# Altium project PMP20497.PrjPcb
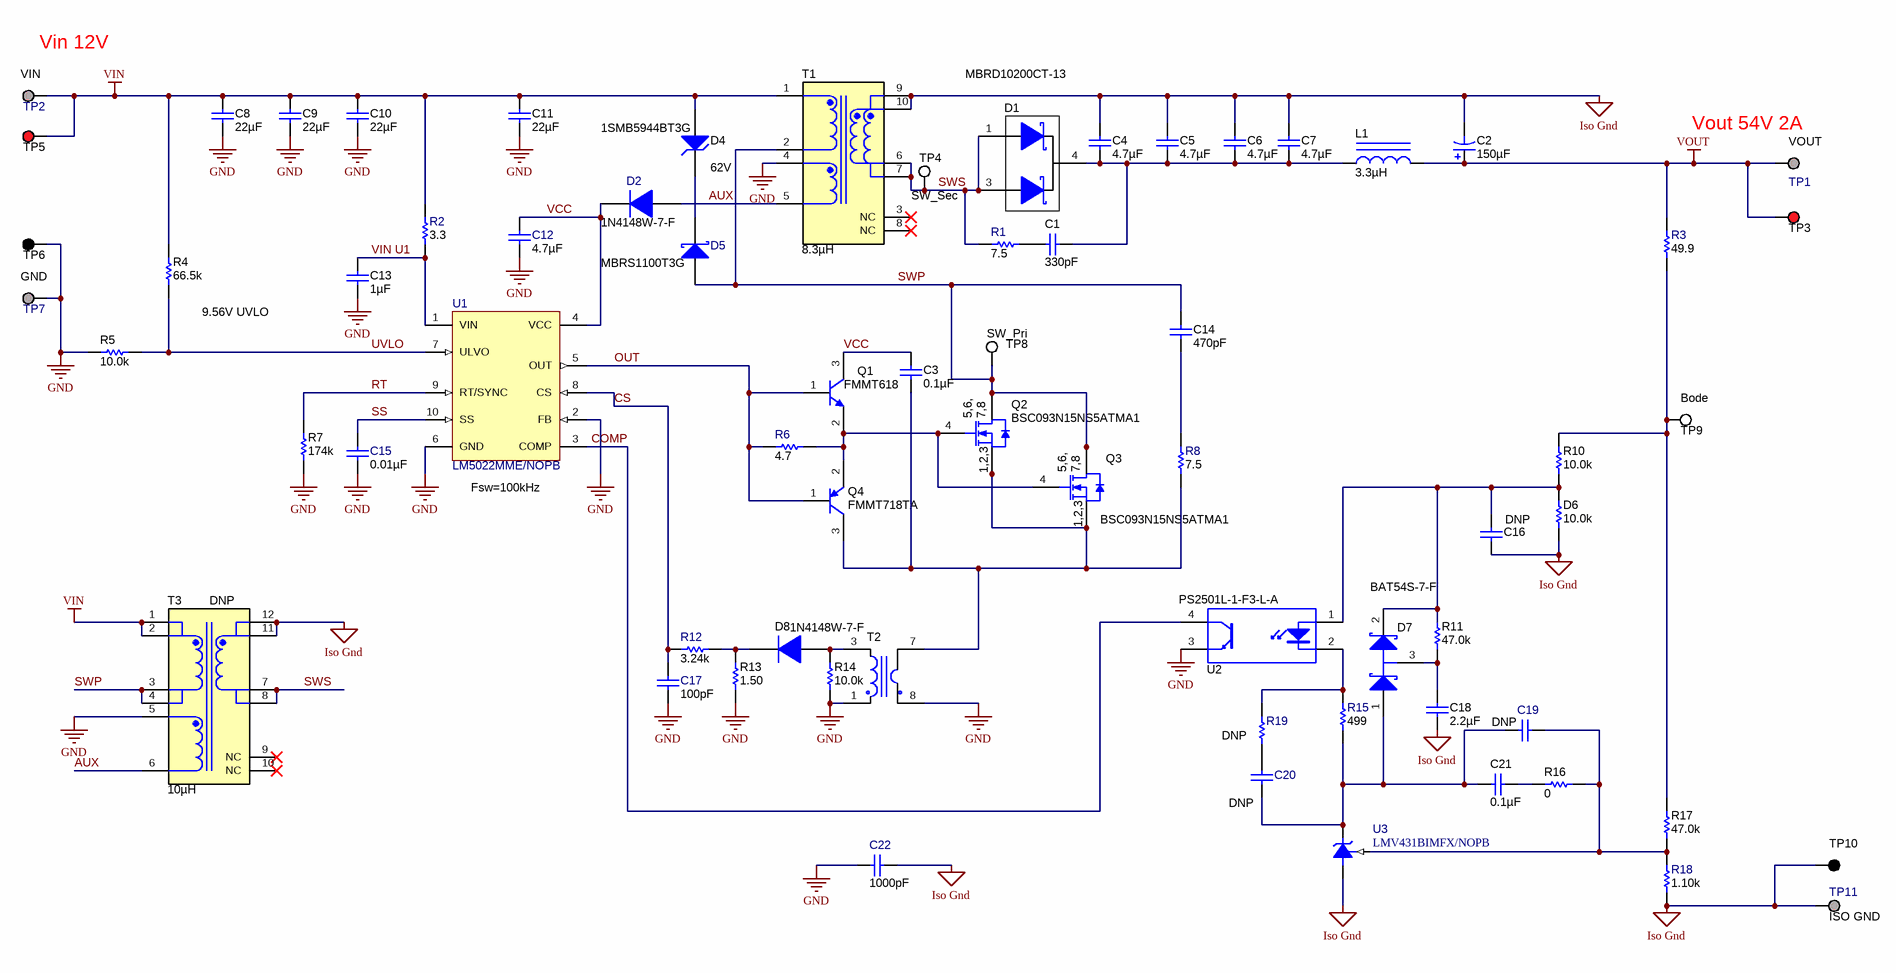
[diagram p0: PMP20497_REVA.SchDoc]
CopyrightYear: 2016; PCB_Layout: Xinyu Dai; PCB_Rev: A; PRJ_Customer: Public Release; PRJ_Engineer: Xinyu Dai; PRJ_Number: PMP20497; PRJ_Title: LM5022 100W Flyback; SCH_Rev: A; TechSupport: http://www.ti.com/support; TID: PMP20497
2 sheets, 82 parts. Net scope: global (net labels, ports and power ports of the same name join across sheets).
Board file: PMP20497_REVA.PcbDoc
Sheets:
  PMP20497_REVA.SchDoc
  PMP20497_REVA_Hardware.SchDoc

## Sheet PMP20497_REVA.SchDoc
size 431 x 279 mm; Date: Not shown in title block; ApprovedBy: Not shown in title block; CheckedBy: Not shown in title block; Author: Not shown in title block; CompanyName: Not shown in title block; Engineer: Not shown in title block; Organization: Not shown in title block; Address1: Not shown in title block; Address2: Not shown in title block; Address3: Not shown in title block; Address4: Not shown in title block; DocumentNumber: 1; Revision: Use project parameter SCH_Rev; SheetNumber: 1; SheetTotal: 2; PageSetup: Record=PageOptions¦CenterHorizontal=True¦CenterVertical=True¦PrintScale=1.00¦XCorrection=1.00¦YCorrection=1.00¦PrintKind=0¦BorderSize=5000000¦LeftOffset=0¦BottomOffset=0¦Orientation=2¦PaperLength=1000¦PaperWidth=1000¦Scale=100¦PaperSource=15¦PrintQuality=600¦MediaType=1¦DitherType=10¦PaperKind=Letter¦PrintScaleMode=1

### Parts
C1  ValueDisplayed: 330pF  [0805L]  (hidden comment: GRM2165C2A331JA01D)
C2  ValueDisplayed: 150µF  [SM_RADIAL_H13]  (hidden comment: EEV-FK1J151Q)
C3  ValueDisplayed: 0.1µF  [0603L]  (hidden comment: GRM188R71C104KA01D)
C4  ValueDisplayed: 4.7µF  [1210_270L]  (hidden comment: GRM32ER71K475KE14L)
C5  ValueDisplayed: 4.7µF  [1210_270L]  (hidden comment: GRM32ER71K475KE14L)
C6  ValueDisplayed: 4.7µF  [1210_270L]  (hidden comment: GRM32ER71K475KE14L)
C7  ValueDisplayed: 4.7µF  [1210_270L]  (hidden comment: GRM32ER71K475KE14L)
C8  ValueDisplayed: 22µF  [1210_270L]  (hidden comment: GRM32ER71E226KE15L)
C9  ValueDisplayed: 22µF  [1210_270L]  (hidden comment: GRM32ER71E226KE15L)
C10  ValueDisplayed: 22µF  [1210_270L]  (hidden comment: GRM32ER71E226KE15L)
C11  ValueDisplayed: 22µF  [1210_270L]  (hidden comment: GRM32ER71E226KE15L)
C12  ValueDisplayed: 4.7µF  [0805L]  (hidden comment: GRM21BR71C475KA73L)
C13  ValueDisplayed: 1µF  [0603L]  (hidden comment: GRM188R71E105KA12D)
C14  ValueDisplayed: 470pF  [0805_HV]  (hidden comment: GRM2165C2A471JA01D)
C15  ValueDisplayed: 0.01µF  [0603L]  (hidden comment: GRM188R71C103KA01D)
C16  DNP  [0603L]
C17  ValueDisplayed: 100pF  [0603L]  (hidden comment: GRM1885C1H101JA01D)
C18  ValueDisplayed: 2.2µF  [0805L]  (hidden comment: UMK212BB7225KG-T)
C19  DNP  [0603L]
C20  DNP  [0603L]
C21  ValueDisplayed: 0.1µF  [0603L]  (hidden comment: GRM188R71E104KA01D)
C22  ValueDisplayed: 1000pF  [1206L]  (hidden comment: GRM31BR73A102KW01L)
D1  MBRD10200CT-13  [DPAK]
D2  (no value)  [SOD-123]
D4  1SMB5944BT3G  value 62V  [SMB]
D5  MBRS1100T3G  [SMB]
D6  ValueDisplayed: 10.0k  [0805L]  (hidden comment: CRCW080510K0FKEA)
D7  BAT54S-7-F  [SOT-23L]
D8  1N4148W-7-F  [SOD-123]
L1  ValueDisplayed: 3.3µH  [SRR6028]  (hidden comment: SRR6028-3R3Y)
Q1  FMMT618  [SOT-23L]
Q2  BSC093N15NS5ATMA1  [PG-TDSON-8]
Q3  BSC093N15NS5ATMA1  [PG-TDSON-8]
Q4  FMMT718TA  [SOT-23L]
R1  ValueDisplayed: 7.5  [2010L]  (hidden comment: CRCW20107R50JNEF)
R2  ValueDisplayed: 3.3  [0805L]  (hidden comment: CRCW08053R30JNEA)
R3  ValueDisplayed: 49.9  [0603L]  (hidden comment: CRCW060349R9FKEA)
R4  ValueDisplayed: 66.5k  [0603L]  (hidden comment: CRCW060366K5FKEA)
R5  value 10.0k  [0603L]  (hidden comment: CRCW060310K0FKEA)
R6  ValueDisplayed: 4.7  [0603L]  (hidden comment: CRCW06034R70JNEA)
R7  ValueDisplayed: 174k  [0603L]  (hidden comment: CRCW0603174KFKEA)
R8  ValueDisplayed: 7.5  [2010L]  (hidden comment: CRCW20107R50JNEF)
R10  ValueDisplayed: 10.0k  [0805L]  (hidden comment: CRCW080510K0FKEA)
R11  ValueDisplayed: 47.0k  [0603L]  (hidden comment: CRCW060347K0FKEA)
R12  ValueDisplayed: 3.24k  [0603L]  (hidden comment: CRCW06033K24FKEA)
R13  ValueDisplayed: 1.50  [0603L]  (hidden comment: CRCW06031R50FKEA)
R14  value 10.0k  [0603L]  (hidden comment: CRCW060310K0FKEA)
R15  ValueDisplayed: 499  [0603L]  (hidden comment: CRCW0603499RFKEA)
R16  ValueDisplayed: 0  [0603]  (hidden comment: CRCW06030000Z0EA)
R17  ValueDisplayed: 47.0k  [0603L]  (hidden comment: CRCW060347K0FKEA)
R18  ValueDisplayed: 1.10k  [0603L]  (hidden comment: CRCW06031K10FKEA)
R19  DNP  [0603L]
T1  ValueDisplayed: 8.3µH  [Pulse_PA4826NL]  (hidden comment: PA4826NL)
T2  PA1005.100NL  [P82xx]  (value not drawn)
T3  DNP  ValueDisplayed: 10µH  [Pulse_PA4621NL]
TP1  VOUT  [Keystone1502-2]
TP2  VIN  [Keystone1502-2]
TP3  5000  [Keystone5000]  (value not drawn)
TP4  SW_Sec  [Keystone5002]
TP5  5000  [Keystone5000]  (value not drawn)
TP6  5001  [Keystone5001]  (value not drawn)
TP7  GND  [Keystone1502-2]
TP8  SW_Pri  [Keystone5002]
TP9  Bode  [Keystone5002]
TP10  5001  [Keystone5001]  (value not drawn)
TP11  ISO GND  [Keystone1502-2]
U1  LM5022MME/NOPB  [MUB10A_N]
U2  PS2501L-1-F3-L-A  [PS2501L]
U3  LMV431BIMFX/NOPB  [MF03A_N]

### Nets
GND: C8.2 C9.2 C10.2 C11.2 C12.2 C13.2 C15.2 C17.2 C22.2 R5.1 R7.1 R13.1 R14.1 T1.4 T2.1 T2.8 T3.5 TP6.1 TP7.1 U1.2(FB) U1.6(GND) U2.3(E)
Iso Gnd: C2.2(-) C4.1 C5.1 C6.1 C7.1 C16.2 C18.2 C22.1 D6.1 R18.2 T1.9 T1.10 T3.11 T3.12 TP10.1 TP11.1 U3.3(A)
VIN: C8.1 C9.1 C10.1 C11.1 D4.2(A) R2.2 R4.2 T1.1 T3.1 T3.2 TP2.1 TP5.1
VOUT: C2.1(+) L1.2 R3.2 TP1.1 TP3.1
AUX: D2.2(A) T1.5 T3.6
COMP: U1.3(COMP) U2.4(C)
CS: C17.1 R12.1 U1.8(CS)
OUT: Q1.1(B) Q4.1(B) R6.1 U1.5(OUT)
RT: R7.2 U1.9(RT/SYNC)
SS: C15.1 U1.10(SS)
SWP: C14.1 D5.2(A) Q2.5(D) Q2.6(D) Q2.7(D) Q2.8(D) Q2.9(D) Q3.5(D) Q3.6(D) Q3.7(D) Q3.8(D) Q3.9(D) T1.2 T3.3 T3.4 TP8.1
SWS: D1.1(A) D1.3(A) R1.2 T1.6 T1.7 T3.7 T3.8 TP4.1
UVLO: R4.1 R5.2 U1.7(ULVO)
VCC: C3.1 C12.1 D2.1(K) Q1.3(C) U1.4(VCC)
VIN U1: C13.1 R2.1 U1.1(VIN)
NetC1_1: C1.1 C4.2 C5.2 C6.2 C7.2 D1.4(K) L1.1
NetC1_2: C1.2 R1.1
NetC3_2: C3.2 Q2.1(S) Q2.2(S) Q2.3(S) Q3.1(S) Q3.2(S) Q3.3(S) Q4.3(C) R8.2 T2.7
NetC14_2: C14.2 R8.1
NetC16_1: C16.1 D6.2 D7.2(K) R10.1 R11.2 U2.1(A)
NetC18_1: C18.1 D7.3(C) R11.1
NetC19_1: C19.1 C20.1 C21.2 D7.1(A) R15.2 U3.2(K)
NetC19_2: C19.2 R16.1 R17.1 R18.1 U3.1(REF)
NetC20_2: C20.2 R19.2
NetC21_1: C21.1 R16.2
NetD4_1: D4.1(K) D5.1(K)
NetD8_1: D8.1(K) R12.2 R13.2
NetD8_2: D8.2(A) R14.2 T2.3
NetQ1_2: Q1.2(E) Q2.4(G) Q3.4(G) Q4.2(E) R6.2
NetR3_1: R3.1 R10.2 R17.2 TP9.1
NetR15_1: R15.1 R19.1 U2.2(K)

Not connected (* = marked no-connect by the designer): T1 3(NC)* 8(NC)*; T3 9(NC)* 10(NC)*

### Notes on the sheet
- (near TP2) Vin 12V
- (near TP1) Vout 54V 2A
- (near R4) 9.56V UVLO
- (near U1) Fsw=100kHz

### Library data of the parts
C1 = GRM2165C2A331JA01D: CAP, CERM, 330 pF, 100 V, +/- 5%, C0G/NP0, 0805; Manufacturer: MuRata; Polarized: N; CompType: Capacitor; Value: 330pF; U/M: EA; Cap_F: 0.00000000033; Tolerance_%: 5; Value1: Unknown; VDC_V: 100; Value2: 100V; TaMin_C: -55; TaMax_C: 125; Cap_Case: 0805; AEC Category: Q200; SizeArea_mm2: 2.5; SizeAreaWB_mm2: 6.75; SizeX_mm: 2; SizeY_mm: 1.25; SizeZ_mm: 1.45
C2 = EEV-FK1J151Q: CAP, AL, 150uF, 63V, +/-20%, 0.16 ohm, SMD; Manufacturer: Panasonic; Polarized: Y; CompType: Capacitor; U/M: EA; Cap_F: 0.00015; Tolerance_%: 20; VDC_V: 63; ESR_Ohm: 0.16; IRMS_A: 0.8; TaMin_C: -55; TaMax_C: 105; Cap_Case: H13
C3 = GRM188R71C104KA01D: CAP, CERM, 0.1 µF, 16 V, +/- 10%, X7R, 0603; Manufacturer: MuRata; Polarized: N; CompType: Capacitor; Value: 0.1uF; U/M: EA; Cap_F: 0.0000001; Tolerance_%: 10; Value1: Unknown; VDC_V: 16; Value2: 16V; TaMin_C: -55; TaMax_C: 125; Cap_Case: 0603; SizeArea_mm2: 1.28; SizeAreaWB_mm2: 4.68; SizeX_mm: 1.6; SizeY_mm: 0.8; SizeZ_mm: 1; AEC Category: Q200
C4-C7 = GRM32ER71K475KE14L: CAP, CERM, 4.7 µF, 80 V, +/- 10%, X7R, 1210; Manufacturer: MuRata; Polarized: N; CompType: Capacitor; Value: 4.7uF; U/M: EA; Cap_F: 0.0000047; Tolerance_%: 10; Value1: Unknown; VDC_V: 80; Value2: 80V; TaMin_C: -55; TaMax_C: 125; Cap_Case: 1210; SizeArea_mm2: 8; SizeAreaWB_mm2: 14.7; SizeX_mm: 3.2; SizeY_mm: 2.5; SizeZ_mm: 2.7; AEC Category: Q200
C8-C11 = GRM32ER71E226KE15L: CAP, CERM, 22 µF, 25 V, +/- 10%, X7R, 1210; Manufacturer: MuRata; Polarized: N; CompType: Capacitor; Value: 22uF; U/M: EA; Cap_F: 0.000022; Tolerance_%: 10; Value1: Unknown; VDC_V: 25; Value2: 25V; TaMin_C: -55; TaMax_C: 125; Cap_Case: 1210; SizeArea_mm2: 8; SizeAreaWB_mm2: 14.7; SizeX_mm: 3.2; SizeY_mm: 2.5; SizeZ_mm: 2.7; AEC Category: Q200
C12 = GRM21BR71C475KA73L: CAP, CERM, 4.7 µF, 16 V, +/- 10%, X7R, 0805; Manufacturer: MuRata; Cap_Case: 0805; ESR_ohm: 0.006; Polarized: N; TaMax_C: 125; TaMin_C: -55; Tolerance_%: 10; VDC_V: 16; Cap_F: 0.0000047; CompType: Capacitor; Value: 4.7uF; U/M: EA; Value1: 0.006 ohm; Value2: 16V; SizeArea_mm2: 2.5; SizeAreaWB_mm2: 6.75; SizeX_mm: 2; SizeY_mm: 1.25; SizeZ_mm: 1.45; AEC Category: Q200
C13 = GRM188R71E105KA12D: CAP, CERM, 1 µF, 25 V, +/- 10%, X7R, 0603; Manufacturer: MuRata; Polarized: N; CompType: Capacitor; Value: 1uF; U/M: EA; Cap_F: 0.000001; Tolerance_%: 10; Value1: Unknown; VDC_V: 25; Value2: 25V; TaMin_C: -55; TaMax_C: 125; Cap_Case: 0603; SizeArea_mm2: 1.28; SizeAreaWB_mm2: 4.68; SizeX_mm: 1.6; SizeY_mm: 0.8; SizeZ_mm: 1; AEC Category: Q200
C14 = GRM2165C2A471JA01D: CAP, CERM, 470 pF, 100 V, +/- 5%, C0G/NP0, 0805; Manufacturer: MuRata; Polarized: N; CompType: Capacitor; Value: 470pF; U/M: EA; Cap_F: 0.00000000047; Tolerance_%: 5; Value1: Unknown; VDC_V: 100; Value2: 100V; TaMin_C: -55; TaMax_C: 125; Cap_Case: 0805; SizeArea_mm2: 2.5; SizeAreaWB_mm2: 6.75; SizeX_mm: 2; SizeY_mm: 1.25; SizeZ_mm: 1.45; AEC Category: Q200
C15 = GRM188R71C103KA01D: CAP, CERM, 0.01 µF, 16 V, +/- 10%, X7R, 0603; Manufacturer: MuRata; Cap_Case: 0603; Polarized: N; TaMax_C: 125; TaMin_C: -55; Tolerance_%: 10; VDC_V: 16; Cap_F: 0.00000001; CompType: Capacitor; Value: 0.01uF; Value1: Unknown; Value2: 16V; U/M: EA; SizeArea_mm2: 1.28; SizeAreaWB_mm2: 4.68; SizeX_mm: 1.6; SizeY_mm: 0.8; SizeZ_mm: 1; AEC Category: Q200
C16 = GRM188R61C105KA93D: CAP, CERM, 1uF, 16V, +/-10%, X5R, 0603; Manufacturer: MuRata; Polarized: N; CompType: Capacitor; ValueDisplayed: 1µF; U/M: EA; Cap_F: 0.000001; Tolerance_%: 10; VDC_V: 16; TaMin_C: -55; TaMax_C: 85; Cap_Case: 0603
C17 = GRM1885C1H101JA01D: CAP, CERM, 100 pF, 50 V, +/- 5%, C0G/NP0, 0603; Manufacturer: MuRata; Cap_Case: 0603; Polarized: N; TaMax_C: 125; TaMin_C: -55; Tolerance_%: 5; VDC_V: 50; Cap_F: 0.0000000001; CompType: Capacitor; Value: 100pF; Value1: Unknown; Value2: 50V; U/M: EA; SizeArea_mm2: 1.28; SizeAreaWB_mm2: 4.68; SizeX_mm: 1.6; SizeY_mm: 0.8; SizeZ_mm: 1; AEC Category: Q200
C18 = UMK212BB7225KG-T: CAP, CERM, 2.2 µF, 50 V, +/- 10%, X7R, 0805; Manufacturer: Taiyo Yuden; Polarized: N; CompType: Capacitor; Value: 2.2uF; U/M: EA; Cap_F: 0.0000022; Tolerance_%: 10; Value1: Unknown; VDC_V: 50; Value2: 50V; TaMin_C: -55; TaMax_C: 125; Cap_Case: 0805; AEC Category: Q200; SizeArea_mm2: 2.5; SizeAreaWB_mm2: 6.75; SizeX_mm: 2; SizeY_mm: 1.25; SizeZ_mm: 1.45
C19 = GRM188R71H332KA01D: CAP, CERM, 3300 pF, 50 V, +/- 10%, X7R, 0603; Manufacturer: MuRata; Cap_Case: 0603; Polarized: N; TaMax_C: 125; TaMin_C: -55; Tolerance_%: 10; VDC_V: 50; Cap_F: 0.0000000033; CompType: Capacitor; Value: 3300pF; Value1: Unknown; Value2: 50V; U/M: EA; AEC Category: Q200; SizeArea_mm2: 1.28; SizeAreaWB_mm2: 4.68; SizeX_mm: 1.6; SizeY_mm: 0.8; SizeZ_mm: 1
C20 = GRM188R71E473KA01D: CAP, CERM, 0.047 µF, 25 V, +/- 10%, X7R, 0603; Manufacturer: MuRata; Cap_Case: 0603; Polarized: N; TaMax_C: 125; TaMin_C: -55; Tolerance_%: 10; VDC_V: 25; Cap_F: 0.000000047; CompType: Capacitor; Value: 0.047uF; Value1: Unknown; Value2: 25V; U/M: EA; AEC Category: Q200
C21 = GRM188R71E104KA01D: CAP, CERM, 0.1 µF, 25 V, +/- 10%, X7R, 0603; Manufacturer: MuRata; Polarized: N; CompType: Capacitor; Value: 0.1uF; U/M: EA; Cap_F: 0.0000001; Tolerance_%: 10; Value1: Unknown; VDC_V: 25; Value2: 25V; TaMin_C: -55; TaMax_C: 125; Cap_Case: 0603; AEC Category: Q200
C22 = GRM31BR73A102KW01L: CAP, CERM, 1000 pF, 1000 V, +/- 10%, X7R, 1206; Manufacturer: MuRata; Cap_Case: 1206; Polarized: N; TaMax_C: 125; TaMin_C: -55; Tolerance_%: 10; VDC_V: 1000; Cap_F: 0.000000001; CompType: Capacitor; Value: 1000pF; Value1: Unknown; Value2: 1000V; U/M: EA; SizeArea_mm2: 5.12; SizeAreaWB_mm2: 10.92; SizeX_mm: 3.2; SizeY_mm: 1.6; SizeZ_mm: 1.35; AEC Category: Q200
D1 = MBRD10200CT-13: Diode, Schottky, 200 V, 5 A, DPAK; Manufacturer: Diodes Inc.; U/M: EA; Value1: 5A; Value: 200V; Vf_V: 0.91; Value2: 0.91V; Io_A: 5; Vr_V: 200; TJmax_C: 175; RJC_CperW: 6; AEC Category: Q101
D2 = 1N4148W-7-F: Diode, Ultrafast, 100V, 0.15A, SOD-123; Manufacturer: Diodes Inc.; U/M: EA; Vf_V: 1.25; Io_A: 0.15; Vr_V: 100; TJmax_C: 150; Value: 1.25V
D4 = 1SMB5944BT3G: Diode, Zener, 62 V, 550 mW, SMB; Manufacturer: ON Semiconductor; U/M: EA; Power_W: 0.55; Value1: 0.55W; RJA_CperW: 226; SymbolCreator: a0412235; Vz_V: 62; AEC Category: Q101
D5 = MBRS1100T3G: Diode, Schottky, 100 V, 1 A, SMB; Manufacturer: ON Semiconductor; RJC_CperW: 22; Vf_V: 0.75; Io_A: 1; Vr_V: 100; TJmax_C: 150; Value: 100V; U/M: EA; Value1: 1A; Value2: 0.75V
D6 R10 = CRCW080510K0FKEA: RES, 10.0 k, 1%, 0.125 W, 0805; Manufacturer: Vishay-Dale; CompType: Resistor; Value: 10.0k; Res_ohm: 10000; Value_Code: 10k0; Tolerance_%: 1; Power_W: 0.125; Value2: 0.125W; VDC_V: 150; TempCo: 100 ppm/C; EIA_Code: E96; U/M: EA; SizeArea_mm2: 2.5; SizeX_mm: 2; SizeY_mm: 1.25; SizeZ_mm: 1.45; AEC Category: Q200
D7 = BAT54S-7-F: Diode, Schottky, 30 V, 0.2 A, SOT-23; Manufacturer: Diodes Inc.; U/M: EA; Vf_V: 0.65; Value: 30V; Value1: 0.2A; Value2: 0.65V; Io_A: 0.2; Vr_V: 30; TJmax_C: 125; SizeAreaWB_mm2: 14; SizeArea_mm2: 7.5; SizeX_mm: 2.5; SizeY_mm: 3; SizeZ_mm: 1.1; AEC Category: Q101
D8 = 1N4148W-7-F: Diode, Ultrafast, 100 V, 0.15 A, SOD-123; Manufacturer: Diodes Inc.; Value: 100V; U/M: EA; Vf_V: 1.25; Io_A: 0.15; Value1: 0.15A; Vr_V: 100; Value2: 1.25V; TJmax_C: 150; AEC Category: Q101
L1 = SRR6028-3R3Y: Inductor, Drum Core, Ferrite, 3.3 µH, 2.5 A, 0.028 ohm, SMD; Manufacturer: Bourns; Value: 3.3uH; Ind_H: 3.3E-6; Imax_A: 2.5; Irms: 2.5A @ 30C rise; Isat: 2.6A @ 35% inductance drop; DCR_ohm: 0.028; Value2: 2.5A; SizeAreaWB_mm2: 77.44; SizeArea_mm2: 46.24; SizeX_mm: 6.8; SizeZ_mm: 2.8; AEC Category: Q200
Q1 = FMMT618: Transistor, NPN, 20V, 1.5A, SOT-23; Manufacturer: Diodes Inc.; CompType: BJT; PNP: 1; NPN: 0; Vceo_V: 20; Vcesat1_V: 0.25; Value: 0.22V; IcRated_A: 0.2; HfeMax: 400; Vce Saturation (Max) @ Ib, Ic: 220mV @ 50mA, 1.5A; Current - Collector Cutoff (Max): 100nA; DC Current Gain (hFE) (Min) @ Ic, Vce: 300 @ 100mA, 2V; Power - Max: 625mW; Frequency - Transition: 180MHz
Q2 Q3 = BSC093N15NS5ATMA1: MOSFET, N-CH, 150 V, 87 A, PG-TDSON-8; Manufacturer: Infineon Technologies; Alternate Manufacturer: None; Value: 150V; U/M: EA; ChType: N; VdsMax_V: 150; Value1: ? ohm; Value2: 33 nC; QgTyp_nC: 33; Vgs_V: 20; IdsMax_A: 87; AEC Category: Q101; SizeAreaWB_mm2: 55.131; SizeArea_mm2: 29.351; SizeX_mm: 5.99; SizeY_mm: 4.9; SizeZ_mm: 1.12
Q4 = FMMT718TA, Diodes Inc.: Transistor, PNP, 20 V, 1.5 A, SOT-23; CompType: BJT; PNP: 1; NPN: 0; Vceo_V: 20; Value: 20 V; IcRated_A: 1.5; Value1: 1.5 A; HfeMax: 6; TaMin_C: -55; TaMax_C: 150; U/M: EA; AEC Category: Q101
R1 R8 = CRCW20107R50JNEF: RES, 7.5, 5%, 0.75 W, AEC-Q200 Grade 0, 2010; Manufacturer: Vishay-Dale; CompType: Resistor; Tolerance_%: 5; VDC_V: 400; Power_W: 0.75; Value: 7.5; Value_Code: 7R50; Value2: 0.75W; TempCo: 200 ppm/C; EIA_Code: E24; U/M: EA; AEC Category: Q200; AEC Qualified: Y; AEC Grade: 0; SizeArea_mm2: 12.5; SizeY_mm: 2.5; SizeZ_mm: 1.66
R2 = CRCW08053R30JNEA: RES, 3.3, 5%, 0.125 W, 0805; Manufacturer: Vishay-Dale; CompType: Resistor; Tolerance_%: 5; VDC_V: 150; Power_W: 0.125; Value: 3.3; Value_Code: 3R30; Value2: 0.125W; EIA_Code: E24; U/M: EA; TempCo: 200 ppm/C; SizeArea_mm2: 2.5; SizeX_mm: 2; SizeY_mm: 1.25; SizeZ_mm: 1.45; AEC Category: Q200
R3 = CRCW060349R9FKEA: RES, 49.9, 1%, 0.1 W, 0603; Manufacturer: Vishay-Dale; CompType: Resistor; Tolerance_%: 1; VDC_V: 75; Power_W: 0.1; Value: 49.9; Value_Code: 49R9; Value2: 0.1W; EIA_Code: E96; U/M: EA; TempCo: 100 ppm/C; SizeArea_mm2: 1.28; SizeX_mm: 1.6; SizeY_mm: 0.8; AEC Category: Q200
R4 = CRCW060366K5FKEA: RES, 66.5 k, 1%, 0.1 W, 0603; Manufacturer: Vishay-Dale; CompType: Resistor; Value: 66.5k; Res_ohm: 66500; Value_Code: 66k5; Tolerance_%: 1; Power_W: 0.1; Value2: 0.1W; VDC_V: 75; TempCo: 100 ppm/C; EIA_Code: E96; U/M: EA; SizeArea_mm2: 1.28; SizeX_mm: 1.6; SizeY_mm: 0.8; AEC Category: Q200
R5 R14 = CRCW060310K0FKEA: RES, 10.0k ohm, 1%, 0.1W, 0603; Manufacturer: Vishay-Dale; CompType: Resistor; Res_ohm: 10000; Value_Code: 10k0; Tolerance_%: 1; Power_W: 0.1; VDC_V: 75; TempCo: 100 ppm/C; EIA_Code: E96; U/M: EA
R6 = CRCW06034R70JNEA: RES, 4.7, 5%, 0.1 W, 0603; Manufacturer: Vishay-Dale; CompType: Resistor; Tolerance_%: 5; VDC_V: 75; Power_W: 0.1; Value: 4.7; Value_Code: 4R70; Value2: 0.1W; TempCo: 200 ppm/C; EIA_Code: E24; U/M: EA; AEC Category: Q200; SizeArea_mm2: 1.28; SizeX_mm: 1.6; SizeY_mm: 0.8; SizeZ_mm: 1
R7 = CRCW0603174KFKEA: RES, 174 k, 1%, 0.1 W, 0603; Manufacturer: Vishay-Dale; CompType: Resistor; Value: 174k; Res_ohm: 174000; Tolerance_%: 1; Power_W: 0.1; Value2: 0.1W; VDC_V: 75; TempCo: 100 ppm/C; EIA_Code: E96; U/M: EA; AEC Category: Q200
R11 = CRCW060347K0FKEA: RES, 47.0 k, 1%, 0.1 W, AEC-Q200 Grade 0, 0603; Manufacturer: Vishay-Dale; CompType: Resistor; Value: 47.0k; Res_ohm: 47000; Value_Code: 47k0; Tolerance_%: 1; Power_W: 0.1; Value2: 0.1W; VDC_V: 75; TempCo: 100 ppm/C; U/M: EA; SizeArea_mm2: 1.28; SizeX_mm: 1.6; SizeY_mm: 0.8; AEC Category: Q200; AEC Qualified: Y; AEC Grade: 0
R12 = CRCW06033K24FKEA: RES, 3.24 k, 1%, 0.1 W, 0603; Manufacturer: Vishay-Dale; CompType: Resistor; Tolerance_%: 1; VDC_V: 75; Power_W: 0.1; Res_ohm: 3240; Value: 3.24k; Value_Code: 3k24; Value2: 0.1W; TempCo: 100 ppm/C; EIA_Code: E96; U/M: EA; AEC Category: Q200; SizeArea_mm2: 1.28; SizeX_mm: 1.6; SizeY_mm: 0.8
R13 = CRCW06031R50FKEA: RES, 1.50, 1%, 0.1 W, 0603; Manufacturer: Vishay-Dale; CompType: Resistor; Value: 1.50; Res_ohm: 1.5; Value_Code: 1R50; Tolerance_%: 1; Power_W: 0.1; Value2: 0.1W; VDC_V: 75; TempCo: 100 ppm/C; EIA_Code: E96; U/M: EA; AEC Category: Q200; SizeArea_mm2: 1.28; SizeX_mm: 1.6; SizeY_mm: 0.8
R15 = CRCW0603499RFKEA: RES, 499, 1%, 0.1 W, 0603; Manufacturer: Vishay-Dale; CompType: Resistor; Tolerance_%: 1; VDC_V: 75; Power_W: 0.1; Value: 499; Value_Code: 499R; Value2: 0.1W; TempCo: 100 ppm/C; EIA_Code: E96; U/M: EA; SizeArea_mm2: 1.28; SizeX_mm: 1.6; SizeY_mm: 0.8; AEC Category: Q200
R16 = CRCW06030000Z0EA: RES, 0, 5%, 0.1 W, 0603; Manufacturer: Vishay-Dale; CompType: Resistor; Value: 0; Value_Code: 0000; Tolerance_%: 5; Power_W: 0.1; Value2: 0.1W; VDC_V: 75; TempCo: 200 ppm/C; EIA_Code: E24; U/M: EA; AEC Category: Q200; SizeArea_mm2: 1.28; SizeX_mm: 1.6; SizeY_mm: 0.8; SizeZ_mm: 1
R17 = CRCW060347K0FKEA: RES, 47.0 k, 1%, 0.1 W, AEC-Q200 Grade 0, 0603; Manufacturer: Vishay-Dale; CompType: Resistor; Value: 47.0k; Res_ohm: 47000; Value_Code: 47k0; Tolerance_%: 1; Power_W: 0.1; Value2: 0.1W; VDC_V: 75; TempCo: 100 ppm/C; U/M: EA; AEC Category: Q200; AEC Qualified: Y; AEC Grade: 0; SizeArea_mm2: 1.28; SizeX_mm: 1.6; SizeY_mm: 0.8
R18 R19 = CRCW06031K10FKEA: RES, 1.10 k, 1%, 0.1 W, 0603; Manufacturer: Vishay-Dale; CompType: Resistor; Tolerance_%: 1; VDC_V: 75; Power_W: 0.1; Res_ohm: 1100; Value: 1.10k; Value_Code: 1k10; Value2: 0.1W; TempCo: 100 ppm/C; EIA_Code: E96; U/M: EA; AEC Category: Q200; SizeArea_mm2: 1.28; SizeX_mm: 1.6; SizeY_mm: 0.8
T1 = PA4826NL: Transformer, 8.3 uH, TH; Manufacturer: Pulse Engineering; SymbolCreator: Altium; Value: 8.3uH; Lp: 8.3; DCR_ohm: 0.0035; LeakageL: 0.15; Ns1toNp: 1.25; Ns2toNp: 0.25; Rs1: 0.04; Rs2: 0.0525; SizeAreaWB_mm2: 1390.25; SizeArea_mm2: 1244.25; SizeX_mm: 39.5; SizeY_mm: 31.5; SizeZ_mm: 20
T2 = PA1005.100NL: SMT Current Sense Tranformer; Manufacturer: Pulse Engineering; SymbolCreator: a0412235; Rs1: 5.5; CompType: Transformer
T3 = PA4621NL: Transformer, 10 uH, TH; Manufacturer: Pulse Engineering; SymbolCreator: Altium; Value: 10uH; Lp: 10; DCR_ohm: 0.0066; Ns1toNp: 2; Rs1: 0.067; SizeAreaWB_mm2: 1006.5; SizeArea_mm2: 883.5; SizeX_mm: 31; SizeY_mm: 28.5; SizeZ_mm: 28
TP1 TP2 TP7 TP11 = 1502-2: Terminal, Turret, TH, Double; Manufacturer: Keystone; Alternate Manufacturer: Any; Alternate PartNumber: Equivalent; CompType: Turret Terminal; U/M: EA
TP3 TP5 = 5000: Test Point, TH, Miniature, Red; Manufacturer: Keystone; Alternate Manufacturer: Any; Alternate PartNumber: Equivalent; CompType: Test Point Loop; U/M: EA
TP4 TP8 TP9 = 5002: Test Point, TH, Miniature, White; Manufacturer: Keystone; Alternate Manufacturer: Any; Alternate PartNumber: Equivalent; CompType: Test Point Loop; U/M: EA
TP6 TP10 = 5001: Test Point, TH, Miniature, Black; Manufacturer: Keystone; Alternate Manufacturer: Any; Alternate PartNumber: Equivalent; CompType: Test Point Loop; U/M: EA
U1 = LM5022MME/NOPB: 60V Low Side Controller for Boost and SEPIC, 10-pin MSOP, Pb-Free; Manufacturer: Texas Instruments; CompType: Switcher; PackageTopMarking: ZXTT*5022; PowerWise: Y
U2 = PS2501L-1-F3-L-A: Optocoupler, 5 kV, 200-400% CTR, SMT; Manufacturer: California Eastern Laboratories; SymbolCreator: a0412235; CTR (Min): 200%; CTR (Max): 400%; Voltage_Isolation_Vrms: 5000V
U3 = LMV431BIMFX/NOPB: Low-Voltage (1.24V) Adjustable Precision Shunt Regulators, 3-pin SOT-23, Pb-Free; Manufacturer: Texas Instruments; PackageTopMarking: RLB*XTT; PowerWise: N; CompType: MiscPower

## Sheet PMP20497_REVA_Hardware.SchDoc
size 431 x 279 mm; Date: Not shown in title block; ApprovedBy: Not shown in title block; CheckedBy: Not shown in title block; Author: Not shown in title block; CompanyName: Not shown in title block; Engineer: Not shown in title block; Organization: Not shown in title block; Address1: Not shown in title block; Address2: Not shown in title block; Address3: Not shown in title block; Address4: Not shown in title block; DocumentNumber: 2; Revision: Use project parameter SCH_Rev; SheetNumber: 2; SheetTotal: 2; PageSetup: Record=PageOptions¦CenterHorizontal=True¦CenterVertical=True¦PrintScale=1.00¦XCorrection=1.00¦YCorrection=1.00¦PrintKind=0¦BorderSize=5000000¦LeftOffset=0¦BottomOffset=0¦Orientation=2¦PaperLength=1000¦PaperWidth=1000¦Scale=100¦PaperSource=15¦PrintQuality=600¦MediaType=1¦DitherType=10¦PaperKind=Letter¦PrintScaleMode=1
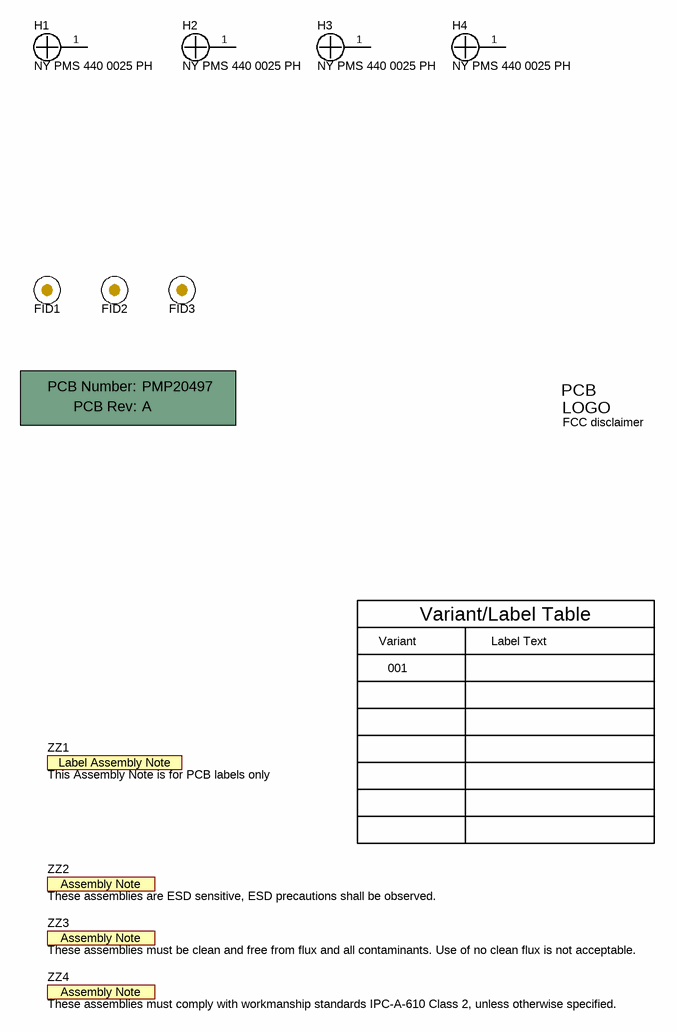
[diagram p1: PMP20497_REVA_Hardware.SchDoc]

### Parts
!PCB1  Printed Circuit Board  (value not drawn)  (mechanical)
FID1  Fiducial  [Fiducial10-20]  (value not drawn)
FID2  Fiducial  [Fiducial10-20]  (value not drawn)
FID3  Fiducial  [Fiducial10-20]  (value not drawn)
H1  NY PMS 440 0025 PH  [NY PMS 440 0025 PH]
H2  NY PMS 440 0025 PH  [NY PMS 440 0025 PH]
H3  NY PMS 440 0025 PH  [NY PMS 440 0025 PH]
H4  NY PMS 440 0025 PH  [NY PMS 440 0025 PH]
Logo1  FCC disclaimer  [FCC_disclaimer]  (no BOM)
ZZ1  This Assembly Note is for PCB labels only  [AssemblyNoteLabel]  (no BOM)
ZZ2  These assemblies are ESD sensitive, ESD precautions shall be observed.  [AssemblyNote]  (no BOM)
ZZ3  These assemblies must be clean and free from flux and all contaminants. Use of no clean flux is not acceptable.  [AssemblyNote]  (no BOM)
ZZ4  These assemblies must comply with workmanship standards IPC-A-610 Class 2, unless otherwise specified.  [AssemblyNote]  (no BOM)

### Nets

Not connected (* = marked no-connect by the designer): H1 1; H2 1; H3 1; H4 1

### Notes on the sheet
- Variant
- Variant/Label Table
- Label Text
- 001

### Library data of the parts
!PCB1 = PCB: Manufacturer: Any; PartNumber: PMP20497; SymbolCreator: a0412235
FID1-FID3 = Fiducial: Fiducial mark.  There is nothing to buy or mount.; SymbolCreator: codlsc
H1-H4 = NY PMS 440 0025 PH: Machine Screw, Round, #4-40 x 1/4, Nylon, Philips panhead; Manufacturer: B&F Fastener Supply; CompType: Hardware; SymbolCreator: codlsc; U/M: EA
Logo1 = FCC_disclaimer: SymbolCreator: codlsc
ZZ1 = AssemblyNoteLabel: SymbolCreator: a0412235
ZZ2-ZZ4 = AssemblyNote: SymbolCreator: codlsc

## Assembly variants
001: not fitted C16 C19 C20 FID1 FID2 FID3 R19 T3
